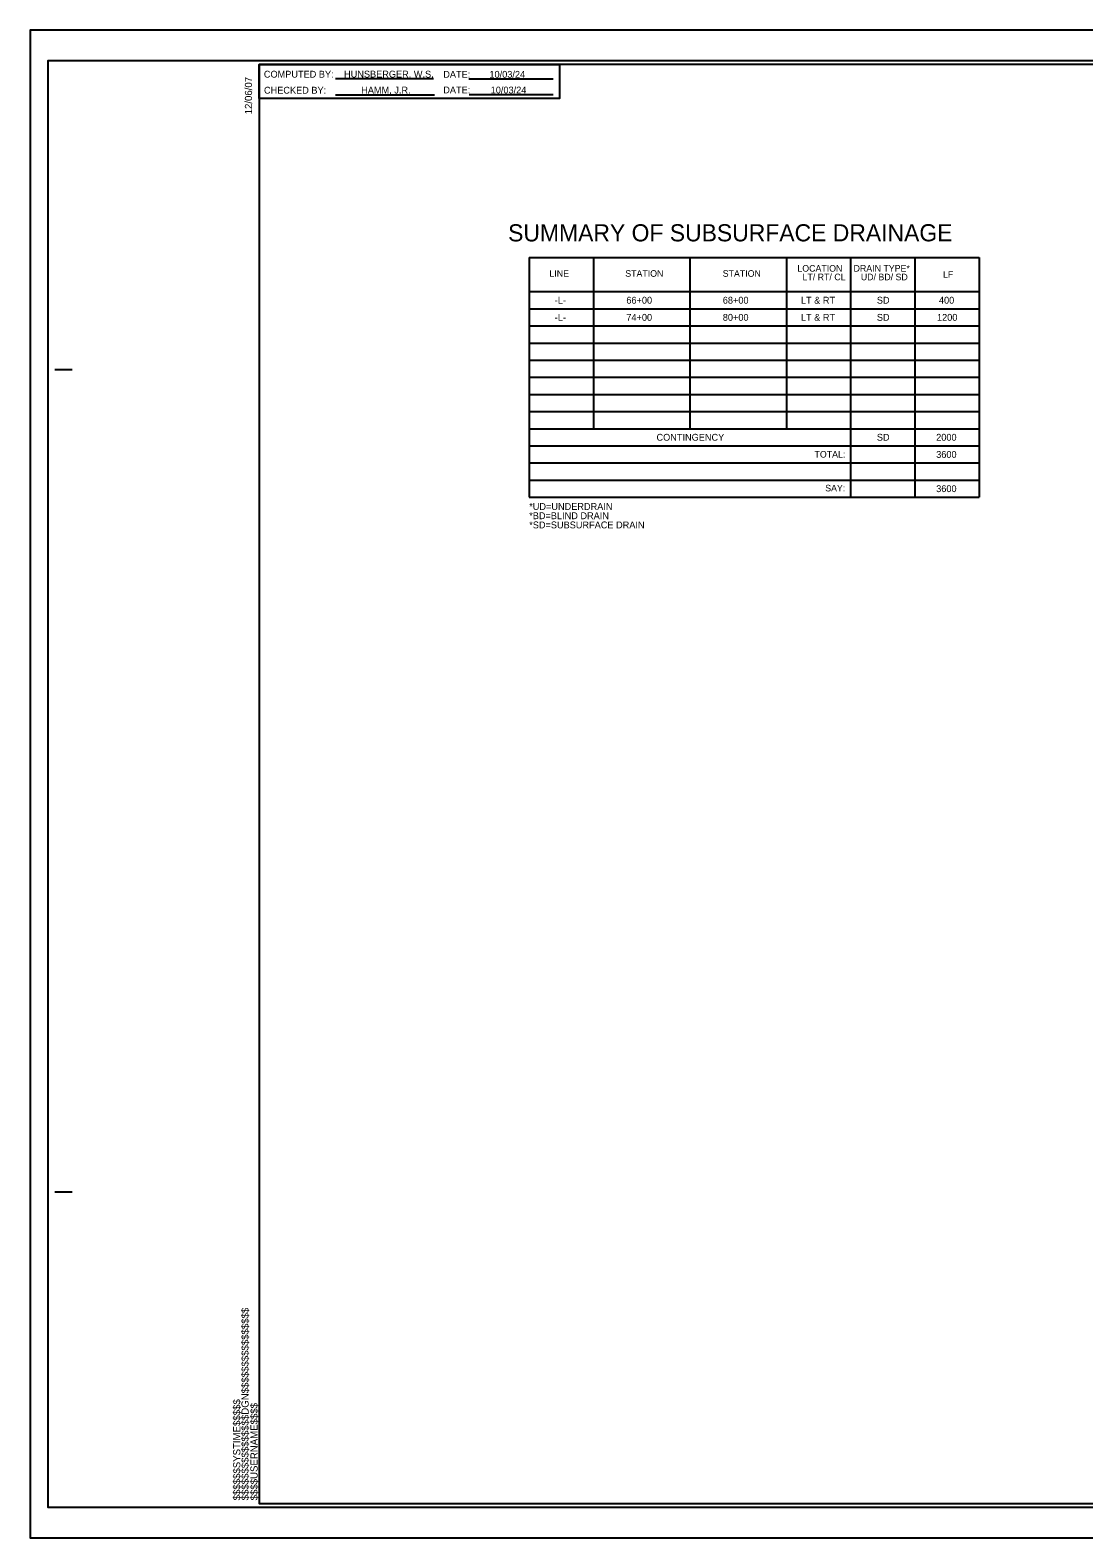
# Model space of a CAD drawing. Extents: x 1729992.2 to 1730025.9, y 539934.2 to 539956.2.
# Drawn here: x 1729992.2 to 1730007.57, y 539934.17 to 539956.17 of the extents above; entities that cross this region are included whole.
import ezdxf

# ---------------------------------------------------------------- set-up
doc = ezdxf.new("R2010")
doc.units = 0
for name, color, linetype in [('Sheet Cutting Line CELL', 7, 'Continuous'), ('Sheet Data Field CELL', 7, 'Continuous'), ('Sheet Plot Border Inside CELL', 7, 'Continuous'), ('Sheet Plot Border Outside CELL', 7, 'Continuous'), ('Sheet Summary Combination CELL', 7, 'Continuous'), ('Sheet Summary Combination Grid CELL', 7, 'Continuous')]:
    doc.layers.add(name, color=color, linetype=linetype)

msp = doc.modelspace()

# ---------------------------------------------------------------- linework, layer by layer
at = {"layer": 'Sheet Cutting Line CELL'}
for p, q in [((1730025.883, 539956.171), (1729992.203, 539956.171)), ((1729992.203, 539956.171), (1729992.203, 539934.171)), ((1729992.203, 539934.171), (1730025.883, 539934.171))]:
    msp.add_line(p, q, dxfattribs=at)
at = {"layer": 'Sheet Plot Border Inside CELL'}
msp.add_lwpolyline([(1730025.793, 539955.722), (1729992.463, 539955.722), (1729992.463, 539934.62), (1730025.793, 539934.62)], close=True, dxfattribs=at)
at = {"layer": 'Sheet Plot Border Outside CELL'}
msp.add_lwpolyline([(1730025.883, 539956.171), (1729992.203, 539956.171), (1729992.203, 539934.171), (1730025.883, 539934.171)], close=True, dxfattribs=at)
at = {"layer": 'Sheet Summary Combination CELL'}
for p, q in [((1729996.656, 539955.463), (1729998.087, 539955.463)), ((1729998.603, 539955.46), (1729999.831, 539955.46)), ((1729996.656, 539955.229), (1729998.101, 539955.229)), ((1729998.606, 539955.23), (1729999.834, 539955.23)), ((1730002.308, 539952.854), (1730002.308, 539952.854)), ((1730002.433, 539952.852), (1730002.433, 539952.852)), ((1730002.614, 539952.856), (1730002.614, 539952.856)), ((1730002.726, 539952.854), (1730002.726, 539952.854)), ((1729992.565, 539951.221), (1729992.815, 539951.221)), ((1729992.565, 539939.221), (1729992.815, 539939.221)), ((1729995.543, 539934.671), (1729995.543, 539934.671))]:
    msp.add_line(p, q, dxfattribs=at)
for points in [[(1730025.543, 539955.671), (1729995.543, 539955.671), (1729995.543, 539934.671), (1730025.543, 539934.671)], [(1729995.543, 539955.671), (1729999.923, 539955.671), (1729999.923, 539955.171), (1729995.543, 539955.171)]]:
    msp.add_lwpolyline(points, close=True, dxfattribs=at)
at = {"layer": 'Sheet Summary Combination Grid CELL'}
for p, q in [((1729999.483, 539952.855), (1730006.048, 539952.855)), ((1729999.483, 539952.855), (1729999.483, 539949.355)), ((1730000.421, 539952.855), (1730000.421, 539950.355)), ((1730001.828, 539952.855), (1730001.828, 539950.355)), ((1730003.234, 539952.855), (1730003.234, 539950.355)), ((1730004.172, 539952.855), (1730004.172, 539949.355)), ((1730005.11, 539952.855), (1730005.11, 539949.355)), ((1730006.048, 539952.855), (1730006.048, 539949.355)), ((1729999.483, 539952.355), (1730006.048, 539952.355)), ((1729999.483, 539952.105), (1730006.048, 539952.105)), ((1729999.483, 539951.855), (1730006.048, 539951.855)), ((1729999.483, 539951.605), (1730006.048, 539951.605)), ((1729999.483, 539951.355), (1730006.048, 539951.355)), ((1729999.483, 539951.105), (1730006.048, 539951.105)), ((1729999.483, 539950.855), (1730006.048, 539950.855)), ((1729999.483, 539950.605), (1730006.048, 539950.605)), ((1729999.483, 539950.355), (1730006.048, 539950.355)), ((1729999.483, 539950.105), (1730006.048, 539950.105)), ((1729999.483, 539949.855), (1730006.048, 539949.855)), ((1729999.483, 539949.605), (1730006.048, 539949.605)), ((1729999.483, 539949.355), (1730006.048, 539949.355))]:
    msp.add_line(p, q, dxfattribs=at)

# ---------------------------------------------------------------- texts
at = {"layer": 'Sheet Data Field CELL'}
for s, p in [('HUNSBERGER, W.S.', (1729996.782, 539955.479)), ('10/03/24', (1729998.903, 539955.476)), ('HAMM, J.R.', (1729997.032, 539955.246)), ('10/03/24', (1729998.921, 539955.247))]:
    msp.add_text(s, height=0.1, dxfattribs=at).set_placement(p)
at = {"layer": 'Sheet Summary Combination CELL'}
for s, height, rotation, p in [('12/06/07', 0.105, 90, (1729995.44, 539954.942)), ('SUMMARY OF SUBSURFACE DRAINAGE', 0.25, 0.0119, (1729999.175, 539953.088)), ('$$$$$$$$$$$$$$$$DGN$$$$$$$$$$$$$$$$', 0.105, 90, (1729995.39, 539934.718)), ('$$$$$$SYSTIME$$$$$', 0.105, 90, (1729995.269, 539934.718)), ('$$$$USERNAME$$$$', 0.105, 90, (1729995.521, 539934.718))]:
    msp.add_text(s, height=height, rotation=rotation, dxfattribs=at).set_placement(p)
for s, height, p in [('COMPUTED BY:', 0.1, (1729995.612, 539955.478)), ('DATE:', 0.1, (1729998.229, 539955.476)), ('CHECKED BY:', 0.1, (1729995.614, 539955.244)), ('DATE:', 0.1, (1729998.229, 539955.248)), ('LINE', 0.096, (1729999.778, 539952.572)), ('STATION', 0.096, (1730000.884, 539952.572)), ('STATION', 0.096, (1730002.306, 539952.572)), ('LOCATION', 0.096, (1730003.395, 539952.647)), ('LT/ RT/ CL', 0.096, (1730003.47, 539952.521)), ('DRAIN TYPE*', 0.096, (1730004.215, 539952.647)), ('UD/ BD/ SD', 0.096, (1730004.321, 539952.521)), ('LF', 0.096, (1730005.519, 539952.557)), ('-L-', 0.1, (1729999.855, 539952.18)), ('66+00', 0.1, (1730000.9, 539952.18)), ('68+00', 0.1, (1730002.307, 539952.18)), ('LT & RT', 0.1, (1730003.447, 539952.18)), ('SD', 0.1, (1730004.554, 539952.18)), ('400', 0.1, (1730005.46, 539952.18)), ('-L-', 0.1, (1729999.855, 539951.93)), ('74+00', 0.1, (1730000.9, 539951.93)), ('80+00', 0.1, (1730002.307, 539951.93)), ('LT & RT', 0.1, (1730003.447, 539951.93)), ('SD', 0.1, (1730004.554, 539951.93)), ('1200', 0.1, (1730005.432, 539951.93)), ('CONTINGENCY', 0.1, (1730001.34, 539950.18)), ('SD', 0.1, (1730004.554, 539950.18)), ('2000', 0.1, (1730005.42, 539950.18)), ('TOTAL:', 0.096, (1730003.645, 539949.934)), ('3600', 0.1, (1730005.42, 539949.93)), ('SAY:', 0.096, (1730003.801, 539949.44)), ('3600', 0.1, (1730005.42, 539949.43)), ('*UD=UNDERDRAIN', 0.1, (1729999.483, 539949.17)), ('*BD=BLIND DRAIN', 0.1, (1729999.483, 539949.035)), ('*SD=SUBSURFACE DRAIN', 0.1, (1729999.483, 539948.901))]:
    msp.add_text(s, height=height, dxfattribs=at).set_placement(p)

doc.saveas('drawing.dxf')
